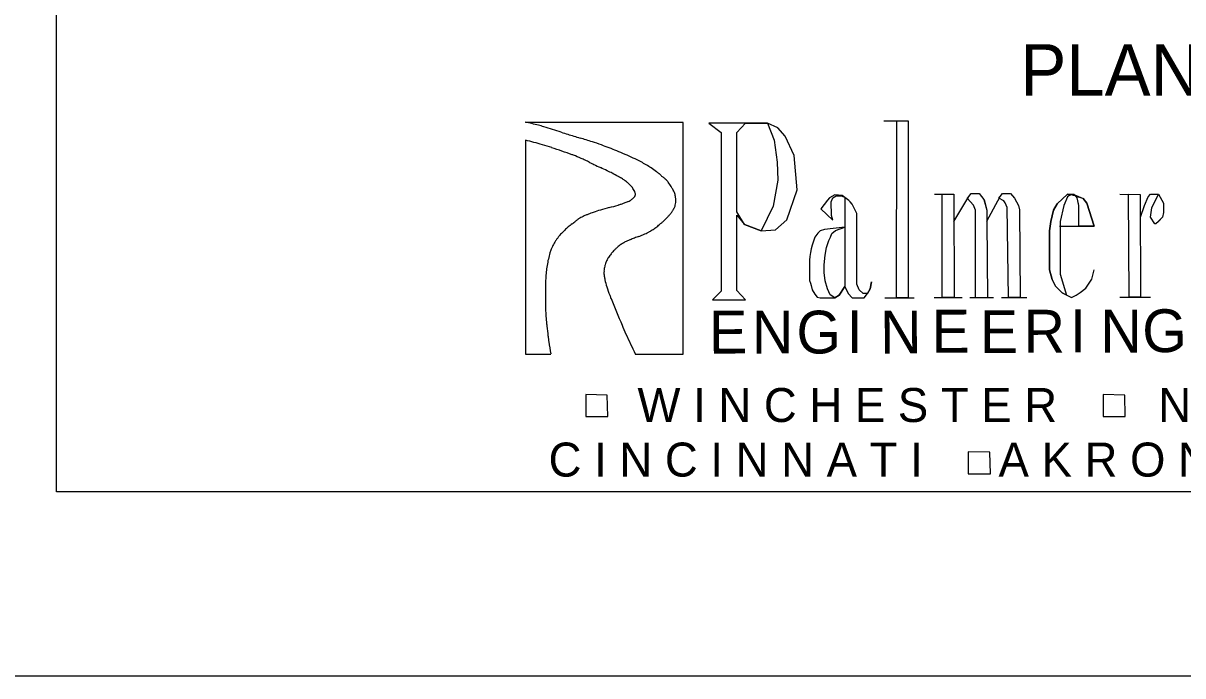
# Model space of a CAD drawing. Extents: x -19.5 to 44.1, y 0 to 22.
# Drawn here: x 1.909 to 5.062, y 0 to 1.775 of the extents above; entities that cross this region are included whole.
import ezdxf

# ---------------------------------------------------------------- set-up
doc = ezdxf.new("R2010")
doc.units = 0
for name, color, linetype in [('SH_Border', 7, 'Continuous'), ('SH_Cut_Line', 7, 'Continuous'), ('SH_Data', 7, 'Continuous'), ('SH_Text', 7, 'Continuous')]:
    doc.layers.add(name, color=color, linetype=linetype)

msp = doc.modelspace()

# ---------------------------------------------------------------- linework, layer by layer
at = {"layer": 'SH_Border'}
msp.add_lwpolyline([(2, 21.5), (33.5, 21.5), (33.5, 0.5), (2, 0.5)], close=True, dxfattribs=at)
at = {"layer": 'SH_Cut_Line'}
msp.add_lwpolyline([(0, 0), (34, 0), (34, 22), (0, 22)], close=True, dxfattribs=at)
at = {"layer": 'SH_Text'}
for p, q in [((3.7032, 1.505), (3.2744, 1.505)), ((3.2744, 1.505), (3.2744, 1.505)), ((3.7032, 0.875), (3.7032, 1.505)), ((3.2744, 1.4563), (3.2744, 1.4563)), ((3.5732, 0.875), (3.7032, 0.875))]:
    msp.add_line(p, q, dxfattribs=at)
for points in [[(3.8729, 1.5025), (3.7729, 1.5025), (3.8066, 1.4775), (3.8066, 1.0463), (3.7829, 1.0225), (3.8729, 1.0225), (3.8491, 1.0475), (3.8491, 1.2525), (3.8704, 1.2275), (3.9154, 1.21), (3.9541, 1.2125), (3.9854, 1.24), (4.0129, 1.3213), (4.0054, 1.415), (3.9804, 1.4675), (3.9604, 1.49), (3.9329, 1.5025), (3.9504, 1.4563), (3.9591, 1.3963), (3.9604, 1.3475), (3.9479, 1.2775), (3.9154, 1.21), (3.8704, 1.2275), (3.8491, 1.2613), (3.8491, 1.4775), (3.8729, 1.5025), (3.9329, 1.5025)], [(4.2841, 1.5088), (4.3154, 1.5088), (4.3154, 1.0275), (4.2829, 1.0275)], [(4.2154, 1.0713), (4.2116, 1.0525), (4.2041, 1.04), (4.1929, 1.04), (4.1816, 1.05), (4.1754, 1.065), (4.1754, 1.2575), (4.1629, 1.2825), (4.1573, 1.2888), (4.1541, 1.2926), (4.1354, 1.3063), (4.1154, 1.3075), (4.1016, 1.3), (4.0954, 1.2938), (4.0779, 1.27), (4.1104, 1.2388), (4.1066, 1.2513), (4.1054, 1.2888), (4.1104, 1.3), (4.1191, 1.305), (4.1341, 1.305), (4.1435, 1.3006), (4.1429, 1.3013), (4.1429, 1.0588), (4.1279, 1.035), (4.1154, 1.0275), (4.1029, 1.0363), (4.0954, 1.0525), (4.0891, 1.0738), (4.0866, 1.0963), (4.0866, 1.1175), (4.0891, 1.1438), (4.0929, 1.165), (4.0991, 1.1838), (4.1035, 1.1931), (4.1079, 1.2025), (4.1179, 1.2113), (4.1429, 1.22), (4.0879, 1.2138), (4.0754, 1.21), (4.0691, 1.2038), (4.0616, 1.1925), (4.0579, 1.1819), (4.0541, 1.1713), (4.0516, 1.1613), (4.0491, 1.1513), (4.0479, 1.1406), (4.0466, 1.13), (4.0466, 1.075), (4.0491, 1.0681), (4.0516, 1.0613), (4.0541, 1.05), (4.0616, 1.0375), (4.0679, 1.03), (4.0754, 1.0275), (4.1154, 1.0275), (4.1279, 1.035), (4.1429, 1.0588), (4.1516, 1.04), (4.1629, 1.0275), (4.1954, 1.0275), (4.2041, 1.04), (4.2116, 1.0525)], [(4.4079, 1.31), (4.4391, 1.31), (4.4404, 1.0288), (4.4079, 1.0288)], [(4.4754, 1.2988), (4.4804, 1.3038), (4.4866, 1.3113), (4.5079, 1.3113), (4.5204, 1.295), (4.5291, 1.2663), (4.5291, 1.2363), (4.5304, 1.0275), (4.4979, 1.0275), (4.4979, 1.2663), (4.4929, 1.28)], [(4.5616, 1.2988), (4.5691, 1.3075), (4.5716, 1.3113), (4.5929, 1.3113), (4.6041, 1.2988), (4.6154, 1.2788), (4.6179, 1.2675), (4.6191, 1.0288), (4.5879, 1.0288), (4.5841, 1.2738), (4.5791, 1.2863), (4.5754, 1.2913)], [(4.7791, 1.2225), (4.7791, 1.2788), (4.7741, 1.3), (4.7679, 1.3063), (4.7641, 1.3063), (4.7579, 1.3075), (4.7516, 1.305), (4.7479, 1.3025), (4.7379, 1.2788), (4.7279, 1.235), (4.7279, 1.0925), (4.7454, 1.035), (4.7341, 1.0413), (4.7154, 1.06), (4.7066, 1.0775), (4.6991, 1.1038), (4.6991, 1.21), (4.7029, 1.235), (4.7104, 1.2663), (4.7204, 1.2838), (4.7479, 1.31), (4.7654, 1.3088), (4.7904, 1.2975), (4.8004, 1.285), (4.8204, 1.2225)], [(4.9141, 1.31), (4.9454, 1.3088), (4.9466, 1.03), (4.9154, 1.03)], [(4.9954, 1.31), (5.0091, 1.285), (5.0091, 1.26), (5.0066, 1.2475), (4.9879, 1.2288), (4.9854, 1.2288), (4.9741, 1.2475), (4.9754, 1.26), (4.9779, 1.2725)], [(3.4384, 0.7649), (3.4384, 0.7049), (3.4984, 0.7049), (3.4971, 0.7636)], [(4.8454, 0.7649), (4.8454, 0.7049), (4.9054, 0.7049), (4.9041, 0.7636)], [(4.4786, 0.609), (4.4786, 0.549), (4.5386, 0.549), (4.5373, 0.6077)]]:
    msp.add_lwpolyline(points, close=True, dxfattribs=at)
for points in [[(4.2491, 1.5088), (4.3154, 1.5088), (4.3154, 1.0275)], [(3.2744, 1.4563), (3.2744, 0.875), (3.3432, 0.875)], [(4.3866, 1.31), (4.4391, 1.31), (4.4404, 1.0288)], [(4.4391, 1.235), (4.4804, 1.3038), (4.4866, 1.3113), (4.5079, 1.3113), (4.5179, 1.2988), (4.5229, 1.2913), (4.5291, 1.2663), (4.5291, 1.2363), (4.5654, 1.3038), (4.5716, 1.3113), (4.5929, 1.3113), (4.6041, 1.2988), (4.6154, 1.2788), (4.6179, 1.2675), (4.6191, 1.0288)], [(4.7266, 1.2225), (4.8204, 1.2225), (4.8004, 1.285), (4.7904, 1.2975), (4.7716, 1.3038), (4.7654, 1.3088), (4.7479, 1.31), (4.7204, 1.2838), (4.7104, 1.2663), (4.7029, 1.235), (4.6991, 1.21), (4.6991, 1.1038), (4.7066, 1.0775), (4.7154, 1.06), (4.7341, 1.0413), (4.7591, 1.0288), (4.7716, 1.035), (4.7829, 1.0425), (4.7979, 1.0538), (4.8141, 1.0788), (4.8204, 1.1038)], [(4.7791, 1.2225), (4.7791, 1.2788), (4.7754, 1.2963), (4.7716, 1.3038)], [(4.8904, 1.31), (4.9454, 1.3088), (4.9466, 1.03)], [(4.9466, 1.2475), (4.9579, 1.2788), (4.9679, 1.3025), (4.9741, 1.31), (4.9954, 1.31), (5.0091, 1.285), (5.0091, 1.26), (5.0066, 1.2475), (4.9954, 1.235), (4.9879, 1.2288), (4.9854, 1.2288), (4.9741, 1.2475), (4.9754, 1.26), (4.9779, 1.2725), (4.9954, 1.31)], [(4.2516, 1.0275), (4.3316, 1.0275)], [(4.3854, 1.0288), (4.4616, 1.0288)], [(4.4829, 1.0288), (4.5466, 1.0288)], [(4.5691, 1.0288), (4.6379, 1.0288)], [(4.8904, 1.03), (4.9741, 1.03)]]:
    msp.add_lwpolyline(points, dxfattribs=at)
for centre, major_axis, ratio, start_param, end_param in [((2.9832, -0.2115), (0, 1.7487), 0.87846, 6.068704, 6.092552), ((3.2495, 1.1801), (0, 0.3244), 0.87846, 6.015491, 6.068704), ((-15.8589, -78.4107), (0, 82.8547), 0.875342, 6.014819, 6.015491), ((2.8849, -0.5173), (0, 2.0232), 0.87846, 6.035373, 6.06218), ((6.0505, 12.5662), (0, 11.4996), 0.87846, 2.873226, 2.875028), ((6.9861, 16.4666), (0, 15.5428), 0.87846, 2.875028, 2.877571), ((1.5376, -6.5123), (0, 8.2585), 0.87846, 6.015499, 6.020286), ((3.3132, 0.8571), (0, 0.6169), 0.87846, 5.967993, 6.015499), ((3.1796, 0.8089), (0, 0.6553), 0.87846, 5.989667, 6.035373), ((-3.7333, -25.2273), (0, 27.8547), 0.87846, 5.987304, 5.989667), ((2.9833, -0.2946), (0, 1.8282), 0.87846, 5.940399, 5.967993), ((3.1811, 0.3365), (0, 1.1582), 0.87846, 5.917138, 5.940399), ((3.3723, 1.3081), (0, 0.1139), 0.87846, 5.950356, 5.987304), ((3.1, 0.4114), (0, 1.0626), 0.87846, 5.926295, 5.950356), ((3.3314, 1.118), (0, 0.3085), 0.87846, 5.881639, 5.926295), ((3.2124, 0.799), (0, 0.6551), 0.87846, 5.859489, 5.881639), ((3.6845, 1.9905), (0, 0.652), 0.87846, 2.717844, 2.740099), ((3.8668, 2.4792), (0, 1.1829), 0.87846, 2.740099, 2.758854), ((3.1734, 0.3136), (0, 1.1827), 0.87846, 5.894118, 5.917138), ((3.3386, 0.7722), (0, 0.6871), 0.87846, 5.855193, 5.894118), ((3.4814, 1.1287), (0, 0.2952), 0.87846, 5.795806, 5.855193), ((3.4449, 1.0501), (0, 0.3842), 0.87846, 5.749826, 5.795806), ((2.9772, -0.0277), (0, 1.5207), 0.87846, 5.883775, 5.898363), ((3.2442, 0.6922), (0, 0.7394), 0.87846, 5.860363, 5.883775), ((3.131, 0.4059), (0, 1.0533), 0.87846, 5.840747, 5.860363), ((3.4307, 1.1261), (0, 0.2564), 0.87846, 5.783384, 5.840747), ((3.4144, 0.9914), (0, 0.4523), 0.87846, 5.707452, 5.749826), ((3.3203, 0.8263), (0, 0.6491), 0.87846, 5.692164, 5.707452), ((3.6225, 1.3391), (0, 0.0317), 0.87846, 5.62293, 5.692164), ((3.622, 1.3384), (0, 0.0326), 0.87846, 5.530169, 5.62293), ((3.6574, 1.3809), (0, 0.026), 0.87846, 2.376805, 2.493109), ((3.6917, 1.4324), (0, 0.0907), 0.87846, 2.493108, 2.531888), ((3.6094, 1.2976), (0, 0.0735), 0.87846, 5.630169, 5.678013), ((3.5694, 1.2381), (0, 0.1484), 0.87846, 5.621033, 5.63017), ((3.4916, 1.2531), (0, 0.1117), 0.87846, 5.696475, 5.783384), ((3.4961, 1.2607), (0, 0.1026), 0.87846, 5.643254, 5.696475), ((3.4366, 1.1697), (0, 0.216), 0.87846, 5.60658, 5.643254), ((3.4624, 1.2064), (0, 0.169), 0.87846, 5.557186, 5.60658), ((3.5341, 1.2982), (0, 0.0461), 0.87846, 5.462631, 5.557186), ((3.5474, 1.3124), (0, 0.0254), 0.87846, 5.357779, 5.462631), ((3.4522, 1.2308), (0, 0.1611), 0.87846, 5.31618, 5.357779), ((2.9913, 0.394), (0, 1.2188), 0.87846, 5.617844, 5.621032), ((3.5755, 1.2415), (0, 0.1415), 0.87846, 5.581326, 5.617844), ((3.5456, 1.2012), (0, 0.1943), 0.87846, 5.55016, 5.581326), ((3.6405, 1.3212), (0, 0.0328), 0.87846, 5.403561, 5.55016), ((3.4605, 1.1516), (0, 0.2988), 0.87846, 5.35501, 5.403561), ((3.5694, 1.2445), (0, 0.1438), 0.87846, 5.295141, 5.35501), ((3.532, 1.3528), (0, 0.0678), 0.87846, 3.510006, 3.625598), ((3.5385, 1.3386), (0, 0.0517), 0.87846, 3.625598, 3.694946), ((3.5305, 1.3534), (0, 0.0691), 0.87846, 3.694946, 3.754926), ((3.537, 1.3428), (0, 0.0561), 0.87846, 3.754926, 3.832303), ((3.5518, 1.3224), (0, 0.0297), 0.87846, 3.832303, 3.938698), ((3.5167, 1.2815), (0, 0.0718), 0.87846, 5.228087, 5.31618), ((3.5614, 1.3117), (0, 0.0144), 0.87846, 3.938698, 4.079149), ((3.5538, 1.3054), (0, 0.0233), 0.87846, 5.073461, 5.228087), ((3.5617, 1.3115), (0, 0.014), 0.87846, 4.079149, 4.221707), ((3.5669, 1.3084), (0, 0.0074), 0.87846, 4.221707, 4.422741), ((3.5641, 1.3098), (0, 0.0108), 0.87846, 4.821391, 5.073461), ((3.5609, 1.3104), (0, 0.0145), 0.87846, 4.422741, 4.566078), ((3.5643, 1.3098), (0, 0.0105), 0.87846, 4.566078, 4.821391), ((3.6056, 1.2716), (0, 0.0946), 0.87846, 5.221294, 5.295141), ((3.6509, 1.3004), (0, 0.0355), 0.87846, 5.021813, 5.221294), ((3.6191, 1.2888), (0, 0.0735), 0.87846, 4.883334, 5.021813), ((3.6258, 1.2901), (0, 0.0657), 0.87846, 4.755052, 4.883334), ((3.6553, 1.2916), (0, 0.0322), 0.87846, 4.571575, 4.755052), ((3.6819, 0.4035), (0, 0.8934), 0.87846, 0.262104, 0.288235), ((3.7053, 0.3041), (0, 0.9963), 0.87846, 0.233797, 0.262104), ((3.3347, 2.0857), (0, 0.8346), 0.87846, 3.372647, 3.406439), ((3.3573, 1.9908), (0, 0.7362), 0.87846, 3.406439, 3.419929), ((3.3464, 2.0341), (0, 0.7812), 0.87846, 3.419929, 3.433025), ((3.5051, 1.4321), (0, 0.1527), 0.87846, 3.433025, 3.510006), ((3.624, 1.306), (0, 0.0713), 0.87846, 4.024354, 4.086609), ((3.628, 1.3026), (0, 0.0656), 0.87846, 4.086609, 4.138734), ((3.6095, 1.3162), (0, 0.0907), 0.87846, 4.138734, 4.183087), ((3.656, 1.2853), (0, 0.0295), 0.87846, 4.183087, 4.241427), ((3.5723, 1.3338), (0, 0.1364), 0.87846, 4.241427, 4.268543), ((3.6587, 1.287), (0, 0.0274), 0.87846, 4.268543, 4.449144), ((3.6314, 1.2954), (0, 0.0596), 0.87846, 4.449144, 4.571575), ((2.0521, 3.4918), (0, 2.735), 0.87846, 3.737876, 3.743109), ((2.6312, 2.5314), (0, 1.5701), 0.87846, 3.743109, 3.745669), ((3.711, 0.7524), (0, 0.5923), 0.87846, 0.599404, 0.60619), ((3.4314, 1.2183), (0, 0.028), 0.87846, 0.455087, 0.599404), ((3.5096, 1.0364), (0, 0.2305), 0.87846, 0.404843, 0.455087), ((3.5358, 0.9667), (0, 0.3064), 0.87846, 0.369872, 0.404843), ((3.5055, 1.0557), (0, 0.2109), 0.87846, 0.327717, 0.369872), ((3.5566, 0.8848), (0, 0.3914), 0.87846, 0.288235, 0.327718), ((3.4883, 1.4654), (0, 0.2938), 0.87846, 3.754086, 3.780496), ((3.4993, 1.4485), (0, 0.2727), 0.87846, 3.780496, 3.811191), ((3.5473, 1.3794), (0, 0.1847), 0.87846, 3.81119, 3.848492), ((3.5378, 1.3921), (0, 0.2013), 0.87846, 3.848492, 3.874263), ((3.3781, 1.5942), (0, 0.4732), 0.87846, 3.874263, 3.891072), ((3.4966, 1.4493), (0, 0.2752), 0.87846, 3.891072, 3.920059), ((3.5783, 1.3549), (0, 0.1427), 0.87846, 3.920059, 3.960321), ((3.6266, 1.3035), (0, 0.0674), 0.87846, 3.960321, 4.024354), ((3.4179, 1.1422), (0, 0.0797), 0.87846, 0.792719, 0.856881), ((3.4552, 1.1003), (0, 0.1393), 0.87846, 0.74169, 0.792719), ((3.556, 0.9751), (0, 0.3092), 0.87846, 0.707435, 0.74169), ((3.6846, 0.8039), (0, 0.5344), 0.87846, 0.683488, 0.707435), ((3.4176, 1.1771), (0, 0.0532), 0.87846, 0.607546, 0.683488), ((3.8061, 0.541), (0, 0.8279), 0.87846, 0.590254, 0.607546), ((3.5231, 1.4156), (0, 0.231), 0.87846, 3.442005, 3.483955), ((3.515, 1.4416), (0, 0.2586), 0.87846, 3.483955, 3.522125), ((3.5449, 1.3566), (0, 0.167), 0.87846, 3.522125, 3.569621), ((3.5161, 1.4283), (0, 0.2459), 0.87846, 3.569621, 3.588674), ((3.5561, 1.3334), (0, 0.1406), 0.87846, 3.588674, 3.613866), ((3.5381, 1.3736), (0, 0.1857), 0.87846, 3.613866, 3.643809), ((3.501, 1.4504), (0, 0.2734), 0.87846, 3.643808, 3.66849), ((3.5189, 1.4153), (0, 0.2328), 0.87846, 3.66849, 3.696658), ((3.5063, 1.4385), (0, 0.2601), 0.87846, 3.696658, 3.723306), ((3.5274, 1.402), (0, 0.2163), 0.87846, 3.723306, 3.754086), ((3.4646, 1.0952), (0, 0.1511), 0.87846, 1.074215, 1.129118), ((3.4168, 1.1248), (0, 0.0891), 0.87846, 1.002719, 1.074215), ((3.4981, 1.0657), (0, 0.199), 0.87846, 0.952796, 1.002719), ((3.4655, 1.092), (0, 0.1535), 0.87846, 0.895951, 0.952796), ((3.5077, 1.0536), (0, 0.215), 0.87846, 0.856881, 0.895951), ((3.5848, 1.0751), (0, 0.1132), 0.87846, 0.595966, 0.645395), ((3.6113, 1.0306), (0, 0.167), 0.87846, 0.55527, 0.595966), ((3.5933, 1.0638), (0, 0.128), 0.87846, 0.470832, 0.55527), ((3.5845, 1.0833), (0, 0.106), 0.87846, 0.378064, 0.470832), ((3.6689, 0.8416), (0, 0.3662), 0.87846, 0.349116, 0.378064), ((3.7631, 0.5468), (0, 0.6798), 0.87846, 0.327872, 0.349116), ((3.7233, 0.6801), (0, 0.539), 0.87846, 0.300413, 0.327872), ((3.5398, 1.0748), (0, 0.2383), 0.87846, 1.249501, 1.322556), ((3.4144, 1.1223), (0, 0.0878), 0.87846, 1.129118, 1.249501), ((3.5587, 1.089), (0, 0.0824), 0.87846, 0.941835, 1.007249), ((3.5984, 1.0561), (0, 0.1383), 0.87846, 0.891343, 0.941835), ((3.5676, 1.0845), (0, 0.0931), 0.87846, 0.829814, 0.891343), ((3.5867, 1.0646), (0, 0.1226), 0.87846, 0.78677, 0.829814), ((3.6018, 1.0475), (0, 0.1469), 0.87846, 0.747442, 0.78677), ((3.5989, 1.0509), (0, 0.1421), 0.87846, 0.693591, 0.747442), ((3.6188, 1.0238), (0, 0.1775), 0.87846, 0.645395, 0.693591), ((3.5604, 1.0683), (0, 0.2626), 0.87846, 1.389057, 1.456641), ((3.5678, 1.0667), (0, 0.2712), 0.87846, 1.322556, 1.389057), ((3.543, 1.0959), (0, 0.0626), 0.87846, 1.383552, 1.501127), ((3.586, 1.0866), (0, 0.1125), 0.87846, 1.327189, 1.383552), ((3.5365, 1.1006), (0, 0.0543), 0.87846, 1.246088, 1.327189), ((3.5566, 1.0929), (0, 0.0786), 0.87846, 1.167276, 1.246088), ((3.5372, 1.1024), (0, 0.0545), 0.87846, 1.072591, 1.167276), ((3.5589, 1.0889), (0, 0.0826), 0.87846, 1.007249, 1.072591), ((4.0015, 1.0372), (0, 0.7658), 0.87846, 1.513412, 1.549016), ((3.5941, 1.0639), (0, 0.3013), 0.87846, 1.456641, 1.513412), ((3.5398, 1.0961), (0, 0.0589), 0.87846, 1.501127, 1.622304), ((3.5305, 1.0956), (0, 0.0484), 0.87846, 1.622304, 1.749821), ((3.6031, 1.1105), (0, 0.1323), 0.87846, 1.749821, 1.826883), ((3.6918, 1.137), (0, 0.2368), 0.87846, 1.826883, 1.911738), ((4.1762, 1.0329), (0, 0.9647), 0.87846, 1.549016, 1.607781), ((3.7962, 1.1791), (0, 0.3628), 0.87846, 1.911738, 1.980277), ((3.7543, 1.1585), (0, 0.3109), 0.87846, 1.980277, 2.010465), ((21.4017, 10.6078), (0, 22.5112), 0.87846, 2.010465, 2.014013), ((3.7539, 1.0151), (0, 0.4837), 0.87846, 1.607781, 1.690785), ((3.8243, 1.0248), (0, 0.5644), 0.87846, 1.690785, 1.701726), ((13.1801, 2.4272), (0, 11.3066), 0.87846, 1.701726, 1.704171), ((4.214, 1.3197), (0, 0.8529), 0.87846, 2.014013, 2.046232), ((3.7601, 0.9884), (0, 0.4871), 0.87846, 1.704171, 1.737317), ((5.9709, 2.3493), (0, 3.1023), 0.87846, 2.046232, 2.065925), ((4.506, 1.1312), (0, 1.3481), 0.87846, 1.737317, 1.761789)]:
    msp.add_ellipse(centre, major_axis=major_axis, ratio=ratio, start_param=start_param, end_param=end_param, dxfattribs=at)

# ---------------------------------------------------------------- texts
at = {"layer": 'SH_Data'}
msp.add_text('PLAN PREPARED BY:', height=0.14, dxfattribs=at).set_placement((4.6202, 1.5775))
at = {"layer": 'SH_Text'}
for s, height, rotation, p in [('E', 0.1164, 0.1223, (3.774, 0.8763)), ('N', 0.1164, 0.1223, (3.8903, 0.8763)), ('G', 0.1164, 0.1223, (4.0115, 0.8763)), ('I', 0.1164, 0.1223, (4.1478, 0.8775)), ('N', 0.1164, 0.1223, (4.239, 0.8763)), ('E', 0.1164, 0.1223, (4.379, 0.8788)), ('E', 0.1164, 0.1223, (4.5103, 0.8775)), ('R', 0.1164, 0.1223, (4.629, 0.8788)), ('I', 0.1164, 0.1223, (4.7553, 0.88)), ('N', 0.1164, 0.1223, (4.8378, 0.8788)), ('G', 0.1164, 0.1223, (4.9515, 0.88)), ('W I N C H E S T E R        N A S H V I L L E      L O U I S V I L L E', 0.0925, 360, (3.5792, 0.6901)), ('C I N C I N N A T I      A K R O N    T A L L A H A S S E E   O R L A N D O', 0.0925, 360, (3.3375, 0.5417))]:
    msp.add_text(s, height=height, rotation=rotation, dxfattribs=at).set_placement(p)

doc.saveas('drawing.dxf')
